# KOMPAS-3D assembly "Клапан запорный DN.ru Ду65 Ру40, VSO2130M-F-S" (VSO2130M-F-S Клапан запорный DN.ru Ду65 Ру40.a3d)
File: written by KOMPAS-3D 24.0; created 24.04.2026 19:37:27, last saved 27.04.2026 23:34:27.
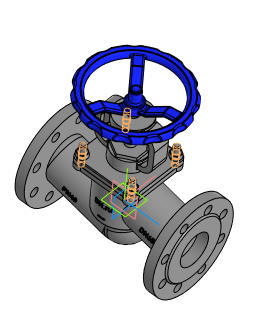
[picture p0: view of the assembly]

Document properties: Автор: DN.ru; Полное имя файла: C:\Работа\ГОТОВЫЕ ИСХОДНИКИ\VSO2130M-F-S Клапан запорный сальниковый DN.ru Ду15-100 Ру40\исходные материалы\DN65\VSO2130M-F-S Клапан запорный DN.ru Ду65 Ру40.a3d

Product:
- Component [detail]: Корпус  | qty 1  | pos. 1  | Масса: 6.9; Автор: R2D2; source file: Korpus.m3d
- Component [detail]: Деталь  | qty 1  | pos. 2  | Масса: 3.382904; Автор: mrdid; source file: rama.m3d
- Component [detail]: Деталь2  | qty 1  | pos. 3  | Масса: 1.724044; Автор: R2D2; additional columns: Типовые; source file: shturval.m3d
- Component [standard]: Шпилька М12-6gx35 ГОСТ 22032-76  | qty 4  | pos. 4  | Масса: 0.03564; Раздел спецификации: Стандартные изделия; Рассекать на разрезах: no
- Component [standard]: Гайка М12-6H ГОСТ 5915-70  | qty 4  | Масса: 0.0184; Раздел спецификации: Стандартные изделия; Рассекать на разрезах: no
- Part/product: Клапан запорный DN.ru Ду65 Ру40  | designation VSO2130M-F-S
    Масса: 24
    Раздел спецификации: Прочие изделия
    Примечание: D090-01985

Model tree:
1. Контекстная связь:1  (with: Контекстная связь (Деталь):1)  (labels: Грань.Твердое тело1)
2. Контекстная связь:2  (with: Смещенная плоскость:4, Контекстная связь (Деталь):2)  (labels: Грань.Твердое тело1)
3. Контекстная связь:3  (with: Контекстная связь (Корпус):3)
4. Контекстная связь:4  (with: Эскиз:2, Ребро.Элемент выдавливания:14, Контекстная связь (Деталь):4)
5. Контекстная связь:5  (with: Контекстная связь (Деталь):5)
6. Массив по концентрической сетке:1  (with: Грань.Элемент выдавливания:1, Грань.Элемент выдавливания:15, Грань.Элемент выдавливания:3, Грань.Элемент выдавливания:16, Грань.Элемент выдавливания:2, Грань.Элемент выдавливания:14)  (labels: Грань.Твердое тело1)  (4 pattern instances)
     Шаг 2 = 360; Угол = 9

Referenced files in C:\Работа\ГОТОВЫЕ ИСХОДНИКИ\VSO2130M-F-S Клапан запорный сальниковый DN.ru Ду15-100 Ру40\исходные материалы\DN65\: Korpus.m3d, rama.m3d, shturval.m3d
Referenced files in C:\Program Files\ASCON\KOMPAS-3D v24\Libs\PolynomLib\DATA\vault\Methods\Kompas\3D\: PLib_Stud_1_900.m3d, PLib_Nut_OST92_900.m3d
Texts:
  Крепежное изделие ГОСТ
  BOSimple***PART:6f4e1f7b-338b-881e-0b64-6bd1e4faf7a4***SHORTLOC:Root±30±20±10±120±10±20[Нет;Без покрытия;Без указания материала;-;12;35;1,75;1,75]
  BOSimple***PART:dfaf85ed-3e43-003f-b29c-9c5b054070d3***SHORTLOC:Root±30±10±20±©{}110±10±50±60[Нет;Без покрытия;Без указания материала;-;12;1,75;19]
  Программные изделия  и базы данных
  VSO2130M-F-S
  Деталь2 Деталь2
  Шпилька М12-6gx35 ГОСТ 22032-76 (1)
  cut1
  Гайка М12-6H ГОСТ 5915-70 (1)
  bcut1
  hole1
  hcut1
  hole2
  Шпилька М12-6gx35 ГОСТ 22032-76 (2)
  Гайка М12-6H ГОСТ 5915-70 (2)
  Шпилька М12-6gx35 ГОСТ 22032-76 (3)
  Гайка М12-6H ГОСТ 5915-70 (3)
  Шпилька М12-6gx35 ГОСТ 22032-76 (4)
  Гайка М12-6H ГОСТ 5915-70 (4)
  Плоскость ZX.Начало координат
  Плоскость XY.Начало координат
  Plane. Начало координат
